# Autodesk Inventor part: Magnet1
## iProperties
Created: 2007-01
Part Number: Magnet1
Cost Center: 0 kg
Material: S235JRG2 (1.0038)
Document SubType Name: Modeling
Designer: M. Fiedler
Manufacturer: Standard
Standards Organization: Custom
Author: M. Fiedler
Einheit: Stück
Ersatzteil: ET AB VT
Grundoberfläche: Rz6.3
WSK a+: 0
WSK a-: -0.1
WSK i+: +0.1
WSK i-: 0
SaveDate: 2007-01-25
SaveTime: 20:46
Masse: 0 kg
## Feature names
1. Drehung1 [Revolution]
2. Abgeleiteter Körper1 [Tagging]
